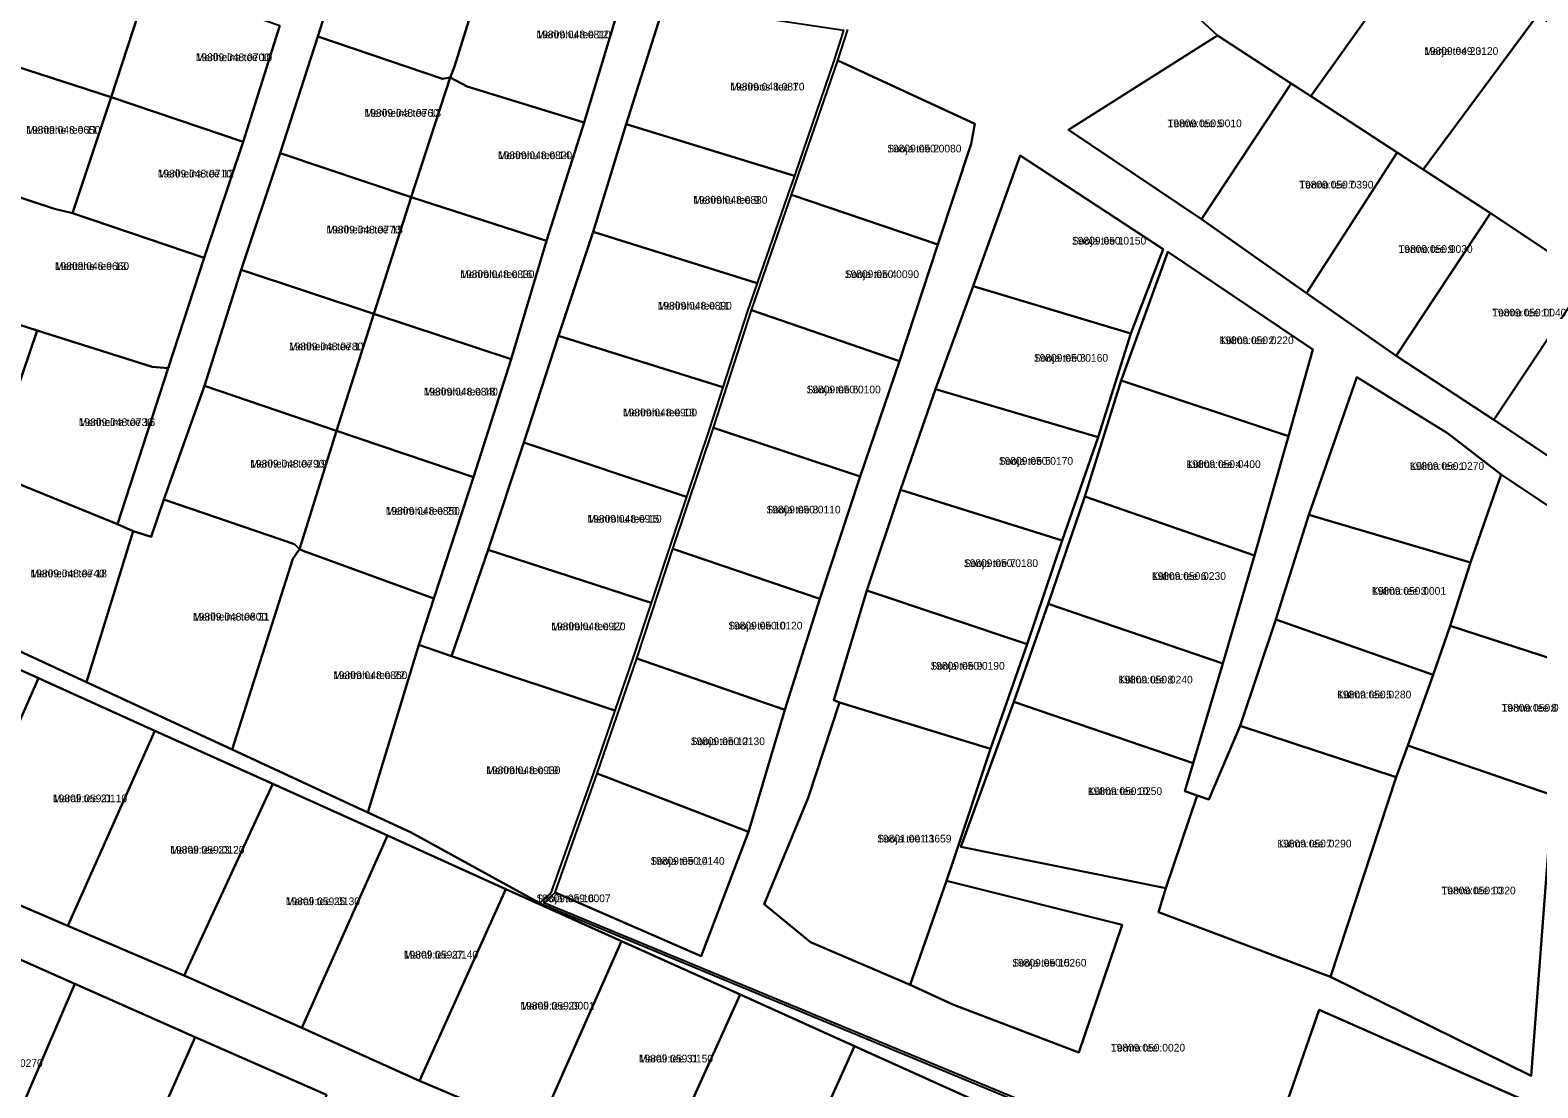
# Model space of a CAD drawing. Extents: x 516875 to 535633, y 6574491 to 6593094.
# Drawn here: x 522233.5 to 522528.1, y 6587985 to 6588191.7 of the extents above; entities that cross this region are included whole.
import ezdxf

# ---------------------------------------------------------------- set-up
doc = ezdxf.new("R2010")
doc.units = 0
for name, color, linetype in [('L_AADRESS', 7, 'Continuous'), ('PIIR', 7, 'Continuous'), ('TUNNUS', 7, 'Continuous')]:
    doc.layers.add(name, color=color, linetype=linetype)

msp = doc.modelspace()

# ---------------------------------------------------------------- linework, layer by layer
at = {"layer": 'PIIR'}
for points in [[(522455.03, 6588200.48), (522475.16, 6588228.69), (522505.52, 6588209.32), (522483.73, 6588178.8), (522479.92, 6588181.28), (522465.48, 6588190.72)], [(522323.25, 6588206.64), (522316.39, 6588184.62), (522315.56, 6588182.5), (522314.07, 6588182.25), (522289.67, 6588190.49), (522297.38, 6588214.66)], [(522256.75, 6588201.43), (522249.29, 6588178.66), (522223.53, 6588187), (522231.06, 6588209.59)], [(522505.52, 6588209.32), (522528.02, 6588194.66), (522505.71, 6588164.48), (522500.6, 6588167.81), (522483.73, 6588178.8)], [(522347.77, 6588198.26), (522348.59, 6588196.38), (522341.74, 6588173.66), (522318.86, 6588180.74), (522315.56, 6588182.5), (522316.39, 6588184.62), (522323.25, 6588206.64)], [(522282.26, 6588192.63), (522275.08, 6588169.92), (522249.29, 6588178.66), (522256.75, 6588201.43)], [(522359.79, 6588196.59), (522392.44, 6588191.74), (522391.62, 6588189.18), (522390.51, 6588185.71), (522382.81, 6588163.28), (522349.97, 6588173.33), (522356.65, 6588194.52), (522357.7, 6588196.38)], [(522505.71, 6588164.48), (522528.02, 6588194.66), (522561.21, 6588172.61), (522540.99, 6588141.27), (522537.95, 6588143.28), (522518.85, 6588155.97)], [(522314.07, 6588182.25), (522315.56, 6588182.5), (522307.9, 6588159.12), (522282.31, 6588167.72), (522289.67, 6588190.49)], [(522479.92, 6588181.28), (522462.35, 6588154.82), (522436.41, 6588172.25), (522465.48, 6588190.72)], [(522249.29, 6588178.66), (522241.75, 6588155.97), (522238.21, 6588156.8), (522216.11, 6588164.03), (522223.53, 6588187)], [(522418.07, 6588173.43), (522417.38, 6588169.52), (522410.86, 6588149.85), (522382.27, 6588159.52), (522391.3, 6588185.82)], [(522318.86, 6588180.74), (522341.74, 6588173.66), (522334.34, 6588150.56), (522307.9, 6588159.12), (522315.56, 6588182.5)], [(522500.48, 6588167.62), (522482.88, 6588140.31), (522462.35, 6588154.82), (522479.92, 6588181.28), (522483.73, 6588178.8), (522500.6, 6588167.81)], [(522275.08, 6588169.92), (522267.45, 6588147.22), (522241.75, 6588155.97), (522249.29, 6588178.66)], [(522382.81, 6588163.28), (522381.48, 6588159.41), (522375.54, 6588142.28), (522343.49, 6588152.31), (522349.97, 6588173.33)], [(522307.9, 6588159.12), (522300.64, 6588136.29), (522274.73, 6588144.91), (522282.31, 6588167.72)], [(522518.85, 6588155.97), (522500.4, 6588128.09), (522482.88, 6588140.31), (522500.48, 6588167.62), (522500.6, 6588167.81), (522505.71, 6588164.48)], [(522454.88, 6588148.9), (522426.91, 6588167.21), (522417.76, 6588141.69), (522410.42, 6588121.56), (522403.56, 6588101.89), (522396.95, 6588082.24), (522390.51, 6588060.81), (522391.62, 6588060.3), (522385.48, 6588041.68), (522376.9, 6588020.91), (522385.95, 6588013.51), (522405.46, 6588005.13), (522413.78, 6588001.32), (522438.42, 6587991.93), (522446.86, 6588016.9), (522412.57, 6588025.5), (522414.04, 6588029.87), (522421.12, 6588051.25), (522428.29, 6588071.73), (522435.15, 6588092.02), (522442.17, 6588112.17), (522448.6, 6588132.44)], [(522454.88, 6588148.9), (522448.6, 6588132.44), (522417.76, 6588141.69), (522426.91, 6588167.21)], [(522238.21, 6588156.8), (522241.75, 6588155.97), (522267.45, 6588147.22), (522260.42, 6588125.68), (522257.32, 6588125.93), (522234.84, 6588133), (522208.79, 6588141.4), (522216.11, 6588164.03)], [(522334.34, 6588150.56), (522327.45, 6588127.43), (522300.64, 6588136.29), (522307.9, 6588159.12)], [(522410.86, 6588149.85), (522403.35, 6588127.07), (522374.46, 6588136.98), (522382.27, 6588159.52)], [(522537.81, 6588143.07), (522519.5, 6588115.6), (522500.4, 6588128.09), (522518.85, 6588155.97), (522537.95, 6588143.28)], [(522375.54, 6588142.28), (522373.67, 6588136.87), (522368.83, 6588121.96), (522336.74, 6588132.02), (522343.49, 6588152.31)], [(522484.14, 6588129.31), (522479.37, 6588112.35), (522446.65, 6588123.26), (522455.8, 6588148.39)], [(522300.64, 6588136.29), (522293.36, 6588113.42), (522267.53, 6588122.22), (522274.73, 6588144.91)], [(522234.84, 6588133), (522226.35, 6588108.22), (522200.79, 6588117.55), (522208.79, 6588141.4)], [(522448.6, 6588132.44), (522442.17, 6588112.17), (522410.42, 6588121.56), (522417.76, 6588141.69)], [(522557.09, 6588130.87), (522538.76, 6588102.74), (522519.5, 6588115.6), (522537.81, 6588143.07), (522537.95, 6588143.28), (522540.99, 6588141.27)], [(522327.45, 6588127.43), (522320.09, 6588104.38), (522293.36, 6588113.42), (522300.64, 6588136.29)], [(522403.35, 6588127.07), (522395.69, 6588104.52), (522367, 6588113.98), (522374.46, 6588136.98)], [(522257.32, 6588125.93), (522260.42, 6588125.68), (522250.51, 6588095.21), (522225.49, 6588105.33), (522226.35, 6588108.22), (522234.84, 6588133)], [(522368.83, 6588121.96), (522366.21, 6588113.87), (522361.72, 6588100.5), (522329.97, 6588111.12), (522336.74, 6588132.02)], [(522479.37, 6588112.35), (522472.74, 6588089.06), (522439.55, 6588100.61), (522446.65, 6588123.26)], [(522510.46, 6588112.97), (522520.94, 6588104.92), (522514.94, 6588087.66), (522483.36, 6588097.03), (522492.72, 6588123.92)], [(522293.36, 6588113.42), (522286.08, 6588090.28), (522285.14, 6588091.26), (522259.58, 6588100), (522267.53, 6588122.22)], [(522442.17, 6588112.17), (522435.15, 6588092.02), (522403.56, 6588101.89), (522410.42, 6588121.56)], [(522320.09, 6588104.38), (522312.38, 6588080.62), (522286.82, 6588089.97), (522286.08, 6588090.28), (522293.36, 6588113.42)], [(522395.69, 6588104.52), (522387.79, 6588080.57), (522359.06, 6588090.33), (522367, 6588113.98)], [(522361.72, 6588100.5), (522358.27, 6588090.22), (522354.84, 6588079.83), (522322.94, 6588090.14), (522329.97, 6588111.12)], [(522250.51, 6588095.21), (522253.6, 6588093.82), (522244.48, 6588064.28), (522213.47, 6588078.63), (522225.49, 6588105.33)], [(522545.36, 6588088.61), (522539.08, 6588066.17), (522510.95, 6588075.29), (522514.94, 6588087.66), (522520.94, 6588104.92)], [(522285.14, 6588091.26), (522286.08, 6588090.28), (522284.77, 6588088.43), (522272.95, 6588051.11), (522244.48, 6588064.28), (522253.6, 6588093.82), (522257.09, 6588092.68), (522259.58, 6588100)], [(522435.15, 6588092.02), (522428.29, 6588071.73), (522396.95, 6588082.24), (522403.56, 6588101.89)], [(522472.74, 6588089.06), (522466.53, 6588067.96), (522432.41, 6588079.63), (522439.55, 6588100.61)], [(522483.36, 6588097.03), (522514.94, 6588087.66), (522510.95, 6588075.29), (522507.64, 6588065.73), (522476.9, 6588076.52)], [(522286.82, 6588089.97), (522312.38, 6588080.62), (522309.41, 6588071.57), (522299.45, 6588038.85), (522272.95, 6588051.11), (522284.77, 6588088.43), (522286.08, 6588090.28)], [(522354.84, 6588079.83), (522351.21, 6588068.81), (522347.74, 6588058.76), (522315.81, 6588069.41), (522322.94, 6588090.14)], [(522387.79, 6588080.57), (522380.98, 6588058.87), (522352, 6588068.92), (522359.06, 6588090.33)], [(522428.29, 6588071.73), (522421.12, 6588051.25), (522391.62, 6588060.3), (522390.51, 6588060.81), (522396.95, 6588082.24)], [(522466.53, 6588067.96), (522460.73, 6588048.48), (522425.68, 6588060.45), (522432.41, 6588079.63)], [(522507.64, 6588065.73), (522502.72, 6588051.89), (522500.44, 6588045.75), (522469.96, 6588055.78), (522476.9, 6588076.52)], [(522212.08, 6588075.43), (522235.1, 6588065.06), (522218.02, 6588026.45), (522195.21, 6588036.14)], [(522539.08, 6588066.17), (522532.26, 6588041.81), (522530.95, 6588042.22), (522502.72, 6588051.89), (522507.64, 6588065.73), (522510.95, 6588075.29)], [(522315.81, 6588069.41), (522347.74, 6588058.76), (522343.47, 6588046.37), (522335.25, 6588023.1), (522333.07, 6588021.09), (522307.81, 6588034.98), (522299.45, 6588038.85), (522309.41, 6588071.57)], [(522380.98, 6588058.87), (522373.88, 6588035.07), (522344.26, 6588046.48), (522352, 6588068.92)], [(522235.1, 6588065.06), (522257.8, 6588054.82), (522240.8, 6588016.65), (522218.02, 6588026.45)], [(522385.48, 6588041.68), (522391.62, 6588060.3), (522421.12, 6588051.25), (522414.04, 6588029.87), (522412.57, 6588025.5), (522405.46, 6588005.13), (522385.95, 6588013.51), (522376.9, 6588020.91)], [(522460.73, 6588048.48), (522459.11, 6588043), (522461.56, 6588042.17), (522455.43, 6588024.06), (522415.36, 6588032.12), (522425.68, 6588060.45)], [(522500.44, 6588045.75), (522487.61, 6588006.69), (522453.96, 6588019.35), (522455.43, 6588024.06), (522461.56, 6588042.17), (522463.8, 6588041.39), (522469.96, 6588055.78)], [(522257.8, 6588054.82), (522280.9, 6588044.4), (522263.56, 6588006.98), (522240.8, 6588016.65)], [(522530.95, 6588042.22), (522526.83, 6587987.38), (522487.61, 6588006.69), (522500.44, 6588045.75), (522502.72, 6588051.89)], [(522280.9, 6588044.4), (522303.28, 6588034.31), (522286.57, 6587996.77), (522263.56, 6588006.98)], [(522373.88, 6588035.07), (522364.62, 6588010.73), (522336.04, 6588023.21), (522344.26, 6588046.48)], [(522303.28, 6588034.31), (522326.44, 6588023.87), (522309.54, 6587986.35), (522286.57, 6587996.77)], [(522349, 6588013.7), (522332.64, 6587976.6), (522309.54, 6587986.35), (522326.44, 6588023.87)], [(522446.86, 6588016.9), (522438.42, 6587991.93), (522413.78, 6588001.32), (522405.46, 6588005.13), (522412.57, 6588025.5)], [(522200.67, 6587973.78), (522220.14, 6588015.08), (522242.17, 6588005.32), (522223.73, 6587962.6), (522219.03, 6587964.81)], [(522372.2, 6588003.24), (522355.54, 6587966.41), (522332.64, 6587976.6), (522349, 6588013.7)], [(522223.73, 6587962.6), (522242.17, 6588005.32), (522265.71, 6587994.89), (522246.46, 6587951.4), (522240.91, 6587954.05)], [(522372.2, 6588003.24), (522394.54, 6587993.16), (522378.06, 6587956.64), (522355.54, 6587966.41)], [(522526.16, 6587982.28), (522520.24, 6587962.71), (522515.58, 6587944.86), (522487.27, 6587958.3), (522474.64, 6587969.4), (522485.36, 6588000.24)], [(522246.46, 6587951.4), (522265.71, 6587994.89), (522291.4, 6587983.67), (522271.04, 6587939.39), (522264.65, 6587942.49)], [(522394.54, 6587993.16), (522417.97, 6587982.6), (522400.68, 6587946.63), (522378.06, 6587956.64)]]:
    msp.add_lwpolyline(points, close=True, dxfattribs=at)
for points in [[(522297.38, 6588214.66), (522289.67, 6588190.49), (522282.31, 6588167.72), (522274.73, 6588144.91), (522267.53, 6588122.22), (522259.58, 6588100), (522257.09, 6588092.68), (522253.6, 6588093.82), (522250.51, 6588095.21), (522260.42, 6588125.68), (522267.45, 6588147.22), (522275.08, 6588169.92), (522282.26, 6588192.63)], [(522455.03, 6588200.48), (522465.48, 6588190.72), (522436.41, 6588172.25), (522462.35, 6588154.82), (522482.88, 6588140.31), (522500.4, 6588128.09), (522519.5, 6588115.6), (522538.76, 6588102.74)], [(522356.65, 6588194.52), (522349.97, 6588173.33), (522343.49, 6588152.31), (522336.74, 6588132.02), (522329.97, 6588111.12), (522322.94, 6588090.14), (522315.81, 6588069.41), (522309.41, 6588071.57), (522312.38, 6588080.62), (522320.09, 6588104.38), (522327.45, 6588127.43), (522334.34, 6588150.56), (522341.74, 6588173.66), (522348.59, 6588196.38)], [(522427.62, 6587982.31), (522333.86, 6588021.2), (522336.04, 6588023.21), (522364.62, 6588010.73), (522373.88, 6588035.07), (522380.98, 6588058.87), (522387.79, 6588080.57), (522395.69, 6588104.52), (522403.35, 6588127.07), (522410.86, 6588149.85), (522417.38, 6588169.52), (522418.07, 6588173.43), (522391.3, 6588185.82), (522393.23, 6588191.85)], [(522545.36, 6588088.61), (522520.94, 6588104.92), (522510.46, 6588112.97), (522492.72, 6588123.92), (522483.36, 6588097.03), (522476.9, 6588076.52), (522469.96, 6588055.78), (522463.8, 6588041.39), (522461.56, 6588042.17), (522459.11, 6588043), (522460.73, 6588048.48), (522466.53, 6588067.96), (522472.74, 6588089.06), (522479.37, 6588112.35), (522484.14, 6588129.31), (522455.8, 6588148.39), (522446.65, 6588123.26), (522439.55, 6588100.61), (522432.41, 6588079.63), (522425.68, 6588060.45), (522415.36, 6588032.12), (522455.43, 6588024.06), (522453.96, 6588019.35), (522487.61, 6588006.69), (522526.83, 6587987.38), (522530.95, 6588042.22)], [(522213.47, 6588078.63), (522244.48, 6588064.28), (522272.95, 6588051.11), (522299.45, 6588038.85), (522307.81, 6588034.98), (522333.07, 6588021.09), (522426.83, 6587982.2), (522540.64, 6587925.34), (522508.33, 6587940.48), (522485.41, 6587951.21), (522462.72, 6587962.42), (522440.36, 6587972.51), (522417.97, 6587982.6), (522394.54, 6587993.16), (522372.2, 6588003.24), (522349, 6588013.7), (522326.44, 6588023.87), (522303.28, 6588034.31), (522280.9, 6588044.4), (522257.8, 6588054.82), (522235.1, 6588065.06), (522212.08, 6588075.43)], [(522218.02, 6588026.45), (522240.8, 6588016.65), (522263.56, 6588006.98), (522286.57, 6587996.77), (522309.54, 6587986.35), (522332.64, 6587976.6)], [(522291.4, 6587983.67), (522265.71, 6587994.89), (522242.17, 6588005.32), (522220.14, 6588015.08)], [(522526.16, 6587982.28), (522485.36, 6588000.24), (522474.64, 6587969.4)]]:
    msp.add_lwpolyline(points, dxfattribs=at)

# ---------------------------------------------------------------- texts
at = {"layer": 'L_AADRESS'}
for s, p in [('Merirohu tee 12', (522332.41, 6588190.15)), ('Marja tee 23', (522505.88, 6588186.9)), ('Meriheina tee 10', (522265.82, 6588185.68)), ('Meriroosi tee 1', (522370.29, 6588179.94)), ('Meriheina tee 13', (522298.82, 6588174.8)), ('Termo tee 5', (522455.75, 6588172.77)), ('Meritähe tee 11', (522232.71, 6588171.49)), ('Merirohu tee 14', (522324.89, 6588166.53)), ('Sooja tee 2', (522400.97, 6588167.84)), ('Meriheina tee 12', (522258.4, 6588162.94)), ('Termo tee 7', (522481.48, 6588160.79)), ('Merirohu tee 9', (522363.05, 6588157.8)), ('Meriheina tee 15', (522291.36, 6588152)), ('Sooja tee 1', (522437.07, 6588149.83)), ('Termo tee 9', (522500.87, 6588148.21)), ('Meritähe tee 13', (522238.29, 6588144.86)), ('Merirohu tee 16', (522317.52, 6588143.28)), ('Sooja tee 4', (522392.67, 6588143.29)), ('Merirohu tee 11', (522356.1, 6588137.13)), ('Termo tee 11', (522519.18, 6588135.78)), ('Meriheina tee 17', (522284.05, 6588129.17)), ('Külma tee 2', (522465.9, 6588130.37)), ('Sooja tee 3', (522429.62, 6588126.93)), ('Merirohu tee 18', (522310.37, 6588120.33)), ('Sooja tee 6', (522385.2, 6588120.75)), ('Merirohu tee 13', (522349.31, 6588116.26)), ('Meriheina tee 16', (522242.96, 6588114.36)), ('Meriheina tee 19', (522276.46, 6588106.25)), ('Sooja tee 5', (522422.78, 6588106.79)), ('Külma tee 4', (522459.45, 6588106.16)), ('Külma tee 1', (522503.11, 6588105.79)), ('Merirohu tee 20', (522302.95, 6588097.02)), ('Merirohu tee 15', (522342.38, 6588095.48)), ('Sooja tee 8', (522377.35, 6588097.28)), ('Sooja tee 7', (522415.94, 6588086.81)), ('Meriheina tee 18', (522233.53, 6588084.8)), ('Külma tee 6', (522452.66, 6588084.29)), ('Külma tee 3', (522495.67, 6588081.38)), ('Meriheina tee 21', (522265.28, 6588076.35)), ('Sooja tee 10', (522369.89, 6588074.6)), ('Merirohu tee 17', (522335.31, 6588074.45)), ('Sooja tee 9', (522409.42, 6588066.74)), ('Merirohu tee 22', (522292.67, 6588064.91)), ('Külma tee 8', (522446.16, 6588064.05)), ('Külma tee 5', (522488.88, 6588061.13)), ('Termo tee 8', (522521.02, 6588058.55)), ('Sooja tee 12', (522362.55, 6588052)), ('Merirohu tee 19', (522322.59, 6588046.33)), ('Külma tee 10', (522440.18, 6588042.25)), ('Marali tee 21', (522237.91, 6588040.84)), ('Marali tee 23', (522260.85, 6588030.79)), ('Sooja tee 11', (522399.01, 6588032.97)), ('Külma tee 7', (522477.2, 6588032)), ('Sooja tee 14', (522354.68, 6588028.61)), ('Termo tee 10', (522509.28, 6588022.83)), ('Marali tee 25', (522283.42, 6588020.72)), ('Sooja tee 16', (522332.4, 6588021.3)), ('Marali tee 27', (522306.5, 6588010.29)), ('Sooja tee 15', (522425.4, 6588008.71)), ('Marali tee 29', (522329.27, 6588000.31)), ('Termo tee', (522444.67, 6587992.11)), ('Marali tee 31', (522352.42, 6587989.98))]:
    msp.add_text(s, height=1.5, dxfattribs=at).set_placement(p)
at = {"layer": 'TUNNUS'}
for s, p in [('19809:048:0810', (522332.41, 6588190.15)), ('19809:049:0120', (522505.88, 6588186.9)), ('19809:048:0700', (522265.82, 6588185.68)), ('19809:048:0870', (522370.29, 6588179.94)), ('19809:048:0760', (522298.82, 6588174.8)), ('19809:050:0010', (522455.75, 6588172.77)), ('19809:048:0650', (522232.71, 6588171.49)), ('19809:048:0820', (522324.89, 6588166.53)), ('19809:050:0080', (522400.97, 6588167.84)), ('19809:048:0710', (522258.4, 6588162.94)), ('19809:050:0390', (522481.48, 6588160.79)), ('19809:048:0880', (522363.05, 6588157.8)), ('19809:048:0770', (522291.36, 6588152)), ('19809:050:0150', (522437.07, 6588149.83)), ('19809:050:0030', (522500.87, 6588148.21)), ('19809:048:0660', (522238.29, 6588144.86)), ('19809:048:0830', (522317.52, 6588143.28)), ('19809:050:0090', (522392.67, 6588143.29)), ('19809:048:0890', (522356.1, 6588137.13)), ('19809:050:0040', (522519.18, 6588135.78)), ('19809:048:0780', (522284.05, 6588129.17)), ('19809:050:0220', (522465.9, 6588130.37)), ('19809:050:0160', (522429.62, 6588126.93)), ('19809:048:0840', (522310.37, 6588120.33)), ('19809:050:0100', (522385.2, 6588120.75)), ('19809:048:0900', (522349.31, 6588116.26)), ('19809:048:0730', (522242.96, 6588114.36)), ('19809:048:0790', (522276.46, 6588106.25)), ('19809:050:0170', (522422.78, 6588106.79)), ('19809:050:0400', (522459.45, 6588106.16)), ('19809:050:0270', (522503.11, 6588105.79)), ('19809:048:0850', (522302.95, 6588097.02)), ('19809:048:0910', (522342.38, 6588095.48)), ('19809:050:0110', (522377.35, 6588097.28)), ('19809:050:0180', (522415.94, 6588086.81)), ('19809:048:0740', (522233.53, 6588084.8)), ('19809:050:0230', (522452.66, 6588084.29)), ('19809:050:0001', (522495.67, 6588081.38)), ('19809:048:0800', (522265.28, 6588076.35)), ('19809:050:0120', (522369.89, 6588074.6)), ('19809:048:0920', (522335.31, 6588074.45)), ('19809:050:0190', (522409.42, 6588066.74)), ('19809:048:0860', (522292.67, 6588064.91)), ('19809:050:0240', (522446.16, 6588064.05)), ('19809:050:0280', (522488.88, 6588061.13)), ('19809:050:0310', (522521.02, 6588058.55)), ('19809:050:0130', (522362.55, 6588052)), ('19809:048:0930', (522322.59, 6588046.33)), ('19809:050:0250', (522440.18, 6588042.25)), ('19809:059:0110', (522237.91, 6588040.84)), ('19809:059:0120', (522260.85, 6588030.79)), ('19801:001:3659', (522399.01, 6588032.97)), ('19809:050:0290', (522477.2, 6588032)), ('19809:050:0140', (522354.68, 6588028.61)), ('19809:050:0320', (522509.28, 6588022.83)), ('19809:059:0130', (522283.42, 6588020.72)), ('19809:059:0007', (522332.4, 6588021.3)), ('19809:059:0140', (522306.5, 6588010.29)), ('19809:050:0260', (522425.4, 6588008.71)), ('19809:059:0001', (522329.27, 6588000.31)), ('19809:050:0020', (522444.67, 6587992.11)), ('19809:059:0150', (522352.42, 6587989.98)), ('19809:059:0270', (522221.42, 6587989.1))]:
    msp.add_text(s, height=1.5, dxfattribs=at).set_placement(p)

doc.saveas('drawing.dxf')
